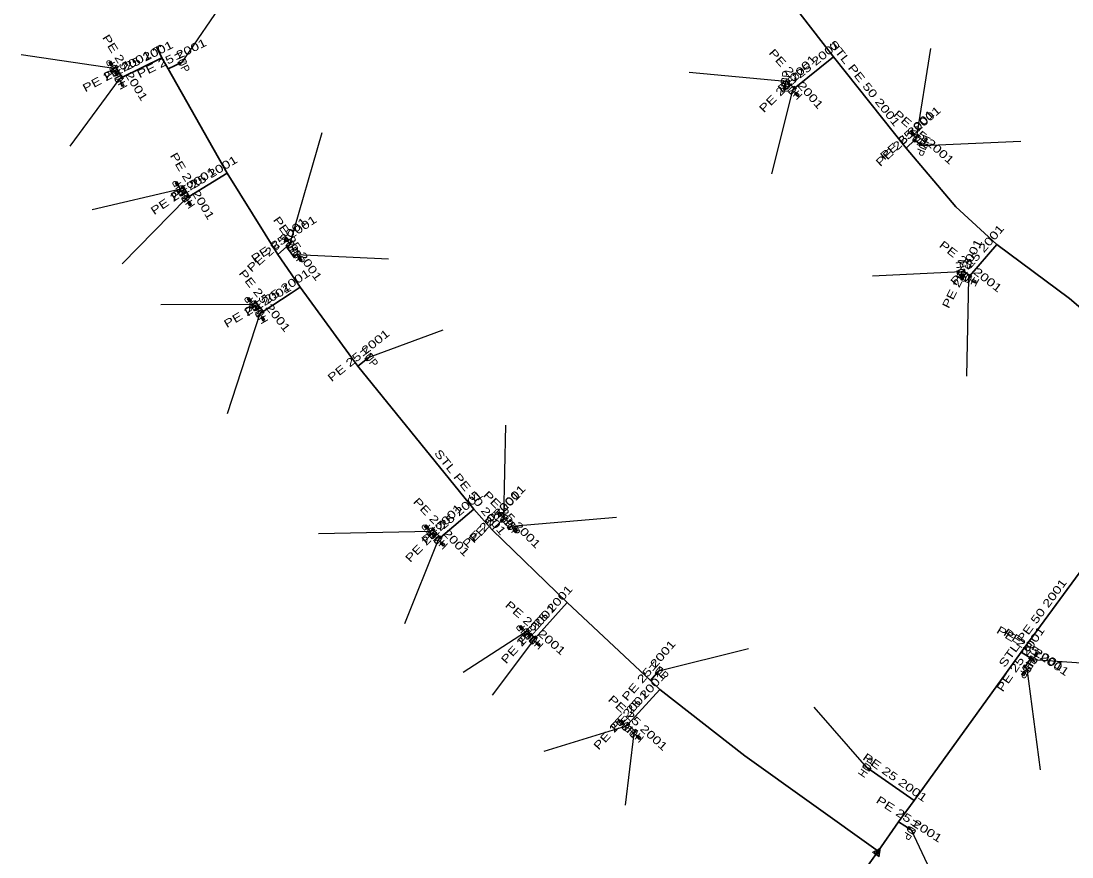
# Model space of a CAD drawing. Extents: x -737484 to -734496, y -1033882 to -1030666.
# Drawn here: x -735033.7 to -734902.5, y -1033583 to -1033478.6 of the extents above; entities that cross this region are included whole.
import ezdxf
from ezdxf.enums import TextEntityAlignment as Align

# ---------------------------------------------------------------- set-up
doc = ezdxf.new("R2010")
doc.units = 0
doc.header["$LTSCALE"] = 0.4
for name, color, linetype, lineweight in [('1', 7, 'Continuous', 13), ('22', 7, 'Continuous', 25), ('5', 7, 'Continuous', 35), ('7', 7, 'Continuous', 35)]:
    doc.layers.add(name, color=color, linetype=linetype, lineweight=lineweight)
doc.layers.add('2', color=7, linetype='Continuous')

msp = doc.modelspace()

# ---------------------------------------------------------------- linework, layer by layer
at = {"layer": '1'}
for p, q in [((-735022.361, -1033484.052), (-735022.546, -1033483.755)), ((-735022.12, -1033484.58), (-735022.384, -1033484.155)), ((-735021.46, -1033485.88), (-735021.225, -1033486.321)), ((-735021.256, -1033486.422), (-735021.091, -1033486.731)), ((-734938.27, -1033486.19), (-734938.313, -1033486.688)), ((-734938.394, -1033486.756), (-734938.425, -1033487.104)), ((-734937.37, -1033487.27), (-734937.016, -1033487.623)), ((-734937.016, -1033487.729), (-734936.768, -1033487.977)), ((-734922.22, -1033492.806), (-734922.45, -1033492.542)), ((-734921.9, -1033493.29), (-734922.228, -1033492.912)), ((-734921.06, -1033494.19), (-734920.864, -1033493.729)), ((-734920.766, -1033493.69), (-734920.629, -1033493.367)), ((-735014.07, -1033499.086), (-735014.26, -1033498.793)), ((-735013.82, -1033499.61), (-735014.092, -1033499.19)), ((-735013.11, -1033500.78), (-735012.83, -1033501.194)), ((-735012.85, -1033501.298), (-735012.654, -1033501.588)), ((-735000.4, -1033506.026), (-735000.59, -1033505.733)), ((-735000.15, -1033506.55), (-735000.422, -1033506.13)), ((-734999.33, -1033507.76), (-734999.043, -1033508.169)), ((-734999.061, -1033508.274), (-734998.86, -1033508.56)), ((-734916.33, -1033509.94), (-734916.26, -1033510.435)), ((-734916.324, -1033510.519), (-734916.275, -1033510.866)), ((-734915.39, -1033510.78), (-734914.944, -1033511.006)), ((-734914.911, -1033511.107), (-734914.599, -1033511.266)), ((-735005.05, -1033513.526), (-735005.28, -1033513.262)), ((-735004.73, -1033514.01), (-735005.058, -1033513.632)), ((-735003.91, -1033515.15), (-735003.66, -1033515.583)), ((-735003.687, -1033515.685), (-735003.512, -1033515.988)), ((-734973.781, -1033540.256), (-734974.033, -1033540.013)), ((-734982.905, -1033541.884), (-734983.148, -1033541.632)), ((-734973.42, -1033540.71), (-734973.779, -1033540.362)), ((-734982.56, -1033542.35), (-734982.907, -1033541.99)), ((-734972.52, -1033541.67), (-734972.191, -1033542.047)), ((-734972.199, -1033542.153), (-734971.969, -1033542.417)), ((-734981.63, -1033543.39), (-734981.27, -1033543.737)), ((-734981.268, -1033543.843), (-734981.016, -1033544.086)), ((-734971.077, -1033554.458), (-734971.315, -1033554.202)), ((-734970.74, -1033554.93), (-734971.08, -1033554.564)), ((-734969.72, -1033555.89), (-734969.348, -1033556.224)), ((-734969.342, -1033556.33), (-734969.082, -1033556.564)), ((-734907.33, -1033558.33), (-734907.072, -1033557.901)), ((-734906.969, -1033557.875), (-734906.789, -1033557.575)), ((-734908.48, -1033559.884), (-734908.66, -1033560.184)), ((-734908.12, -1033559.43), (-734908.377, -1033559.858)), ((-734958.559, -1033566.239), (-734958.831, -1033566.019)), ((-734958.16, -1033566.66), (-734958.548, -1033566.345)), ((-734957.18, -1033567.53), (-734956.802, -1033567.858)), ((-734956.795, -1033567.963), (-734956.531, -1033568.193))]:
    msp.add_line(p, q, dxfattribs=at)
msp.add_lwpolyline([(-735017.162, -1033482.329), (-735017.275, -1033482.106), (-735016.384, -1033481.653), (-735016.27, -1033481.875)], dxfattribs=at)
for points in [[(-735022.649, -1033483.731), (-735022.777, -1033483.811), (-735022.512, -1033484.235), (-735022.384, -1033484.155)], [(-735022.649, -1033483.731), (-735022.522, -1033483.652), (-735022.257, -1033484.076), (-735022.384, -1033484.155)], [(-735022.598, -1033483.744), (-735022.534, -1033483.704), (-735022.309, -1033484.065), (-735022.373, -1033484.104)], [(-735013.248, -1033483.371), (-735013.072, -1033483.73), (-735014.147, -1033483.809), (-735013.971, -1033484.168)], [(-735022.453, -1033485.003), (-735022.653, -1033484.656), (-735021.586, -1033484.503), (-735021.786, -1033484.156)], [(-735021.807, -1033486.29), (-735021.995, -1033485.937), (-735020.924, -1033485.82), (-735021.112, -1033485.467)], [(-735020.99, -1033486.762), (-735021.122, -1033486.833), (-735021.357, -1033486.391), (-735021.225, -1033486.321)], [(-735021.041, -1033486.746), (-735021.107, -1033486.781), (-735021.306, -1033486.406), (-735021.24, -1033486.371)], [(-735020.99, -1033486.762), (-735020.858, -1033486.692), (-735021.092, -1033486.251), (-735021.225, -1033486.321)], [(-734938.784, -1033486.344), (-734938.749, -1033485.946), (-734937.788, -1033486.431), (-734937.753, -1033486.033)], [(-734938.357, -1033487.186), (-734938.506, -1033487.173), (-734938.463, -1033486.675), (-734938.313, -1033486.688)], [(-734938.39, -1033487.145), (-734938.465, -1033487.138), (-734938.428, -1033486.715), (-734938.353, -1033486.721)], [(-734938.357, -1033487.186), (-734938.207, -1033487.199), (-734938.164, -1033486.701), (-734938.313, -1033486.688)], [(-734937.581, -1033487.764), (-734937.863, -1033487.482), (-734936.874, -1033487.057), (-734937.156, -1033486.775)], [(-734936.662, -1033487.977), (-734936.768, -1033488.083), (-734937.122, -1033487.729), (-734937.016, -1033487.623)], [(-734936.715, -1033487.976), (-734936.768, -1033488.029), (-734937.069, -1033487.728), (-734937.016, -1033487.675)], [(-734936.662, -1033487.977), (-734936.556, -1033487.871), (-734936.91, -1033487.517), (-734937.016, -1033487.623)], [(-734922.556, -1033492.535), (-734922.669, -1033492.633), (-734922.341, -1033493.011), (-734922.228, -1033492.912)], [(-734922.556, -1033492.535), (-734922.442, -1033492.436), (-734922.114, -1033492.814), (-734922.228, -1033492.912)], [(-734922.503, -1033492.539), (-734922.446, -1033492.49), (-734922.167, -1033492.811), (-734922.224, -1033492.86)], [(-734921.653, -1033492.811), (-734921.391, -1033493.112), (-734922.408, -1033493.467), (-734922.146, -1033493.768)], [(-734920.521, -1033494.2), (-734920.677, -1033494.568), (-734921.442, -1033493.809), (-734921.598, -1033494.177)], [(-734920.669, -1033493.269), (-734920.807, -1033493.21), (-734921.002, -1033493.671), (-734920.864, -1033493.729)], [(-734920.669, -1033493.269), (-734920.531, -1033493.328), (-734920.726, -1033493.788), (-734920.864, -1033493.729)], [(-734920.65, -1033493.318), (-734920.581, -1033493.348), (-734920.747, -1033493.739), (-734920.816, -1033493.71)], [(-735014.364, -1033498.771), (-735014.49, -1033498.853), (-735014.218, -1033499.272), (-735014.092, -1033499.19)], [(-735014.364, -1033498.771), (-735014.238, -1033498.689), (-735013.966, -1033499.108), (-735014.092, -1033499.19)], [(-735014.129, -1033500.05), (-735014.347, -1033499.714), (-735013.29, -1033499.505), (-735013.508, -1033499.169)], [(-735014.312, -1033498.783), (-735014.25, -1033498.742), (-735014.018, -1033499.098), (-735014.081, -1033499.139)], [(-735013.412, -1033501.225), (-735013.636, -1033500.893), (-735012.583, -1033500.666), (-735012.807, -1033500.334)], [(-735012.55, -1033501.609), (-735012.675, -1033501.692), (-735012.954, -1033501.278), (-735012.83, -1033501.194)], [(-735012.602, -1033501.598), (-735012.664, -1033501.64), (-735012.902, -1033501.287), (-735012.84, -1033501.245)], [(-735012.55, -1033501.609), (-735012.426, -1033501.525), (-735012.706, -1033501.11), (-735012.83, -1033501.194)], [(-735000.694, -1033505.711), (-735000.82, -1033505.793), (-735000.548, -1033506.212), (-735000.422, -1033506.13)], [(-735000.694, -1033505.711), (-735000.568, -1033505.629), (-735000.296, -1033506.048), (-735000.422, -1033506.13)], [(-734999.838, -1033506.108), (-734999.62, -1033506.444), (-735000.677, -1033506.653), (-735000.459, -1033506.989)], [(-735000.642, -1033505.723), (-735000.58, -1033505.682), (-735000.348, -1033506.038), (-735000.411, -1033506.079)], [(-734999.034, -1033507.309), (-734998.804, -1033507.637), (-734999.853, -1033507.882), (-734999.623, -1033508.21)], [(-734998.756, -1033508.579), (-734998.879, -1033508.665), (-734999.166, -1033508.255), (-734999.043, -1033508.169)], [(-734998.808, -1033508.569), (-734998.869, -1033508.612), (-734999.113, -1033508.264), (-734999.052, -1033508.221)], [(-734998.756, -1033508.579), (-734998.633, -1033508.493), (-734998.92, -1033508.083), (-734999.043, -1033508.169)], [(-734915.861, -1033509.671), (-734915.806, -1033510.067), (-734916.851, -1033509.81), (-734916.796, -1033510.206)], [(-734916.19, -1033510.93), (-734916.339, -1033510.951), (-734916.408, -1033510.456), (-734916.26, -1033510.435)], [(-734916.232, -1033510.897), (-734916.307, -1033510.908), (-734916.366, -1033510.487), (-734916.291, -1033510.476)], [(-734916.19, -1033510.93), (-734916.042, -1033510.909), (-734916.111, -1033510.414), (-734916.26, -1033510.435)], [(-734915.438, -1033511.316), (-734915.795, -1033511.134), (-734914.984, -1033510.425), (-734915.341, -1033510.243)], [(-734914.498, -1033511.233), (-734914.567, -1033511.367), (-734915.012, -1033511.14), (-734914.944, -1033511.006)], [(-734914.549, -1033511.249), (-734914.583, -1033511.316), (-734914.962, -1033511.123), (-734914.928, -1033511.056)], [(-734914.498, -1033511.233), (-734914.43, -1033511.1), (-734914.876, -1033510.873), (-734914.944, -1033511.006)], [(-735005.386, -1033513.255), (-735005.499, -1033513.353), (-735005.171, -1033513.731), (-735005.058, -1033513.632)], [(-735005.386, -1033513.255), (-735005.272, -1033513.156), (-735004.944, -1033513.534), (-735005.058, -1033513.632)], [(-735005.333, -1033513.259), (-735005.276, -1033513.21), (-735004.997, -1033513.531), (-735005.054, -1033513.58)], [(-735004.976, -1033514.487), (-735005.238, -1033514.186), (-735004.221, -1033513.831), (-735004.483, -1033513.53)], [(-735004.243, -1033515.573), (-735004.443, -1033515.226), (-735003.376, -1033515.073), (-735003.576, -1033514.726)], [(-735003.41, -1033516.016), (-735003.539, -1033516.091), (-735003.789, -1033515.658), (-735003.66, -1033515.583)], [(-735003.461, -1033516.001), (-735003.525, -1033516.039), (-735003.738, -1033515.671), (-735003.673, -1033515.633)], [(-735003.41, -1033516.016), (-735003.28, -1033515.941), (-735003.53, -1033515.508), (-735003.66, -1033515.583)], [(-734989.996, -1033520.129), (-734989.744, -1033520.44), (-734990.773, -1033520.759), (-734990.521, -1033521.07)], [(-734974.139, -1033540.015), (-734974.243, -1033540.123), (-734973.883, -1033540.47), (-734973.779, -1033540.362)], [(-734974.139, -1033540.015), (-734974.035, -1033539.907), (-734973.675, -1033540.254), (-734973.779, -1033540.362)], [(-734974.086, -1033540.015), (-734974.034, -1033539.961), (-734973.728, -1033540.256), (-734973.78, -1033540.31)], [(-734973.215, -1033540.21), (-734972.927, -1033540.488), (-734973.91, -1033540.929), (-734973.622, -1033541.207)], [(-734983.254, -1033541.63), (-734983.362, -1033541.734), (-734983.015, -1033542.094), (-734982.907, -1033541.99)], [(-734983.254, -1033541.63), (-734983.146, -1033541.526), (-734982.799, -1033541.886), (-734982.907, -1033541.99)], [(-734983.201, -1033541.632), (-734983.147, -1033541.58), (-734982.852, -1033541.885), (-734982.906, -1033541.938)], [(-734972.272, -1033541.191), (-734972.01, -1033541.492), (-734973.027, -1033541.847), (-734972.765, -1033542.148)], [(-734982.779, -1033542.84), (-734983.057, -1033542.552), (-734982.06, -1033542.145), (-734982.338, -1033541.857)], [(-734981.833, -1033543.887), (-734982.121, -1033543.609), (-734981.138, -1033543.168), (-734981.426, -1033542.89)], [(-734971.863, -1033542.424), (-734971.977, -1033542.523), (-734972.305, -1033542.145), (-734972.191, -1033542.047)], [(-734971.916, -1033542.42), (-734971.973, -1033542.469), (-734972.252, -1033542.148), (-734972.195, -1033542.099)], [(-734971.863, -1033542.424), (-734971.75, -1033542.326), (-734972.078, -1033541.948), (-734972.191, -1033542.047)], [(-734980.91, -1033544.084), (-734981.014, -1033544.192), (-734981.374, -1033543.845), (-734981.27, -1033543.737)], [(-734980.963, -1033544.084), (-734981.015, -1033544.138), (-734981.321, -1033543.843), (-734981.269, -1033543.789)], [(-734980.91, -1033544.084), (-734980.806, -1033543.976), (-734981.166, -1033543.629), (-734981.27, -1033543.737)], [(-734971.421, -1033554.198), (-734971.531, -1033554.3), (-734971.19, -1033554.666), (-734971.08, -1033554.564)], [(-734971.421, -1033554.198), (-734971.312, -1033554.096), (-734970.971, -1033554.462), (-734971.08, -1033554.564)], [(-734971.369, -1033554.201), (-734971.314, -1033554.15), (-734971.024, -1033554.46), (-734971.079, -1033554.512)], [(-734970.959, -1033555.421), (-734971.237, -1033555.133), (-734970.24, -1033554.726), (-734970.518, -1033554.438)], [(-734969.904, -1033556.395), (-734970.202, -1033556.127), (-734969.235, -1033555.652), (-734969.533, -1033555.384)], [(-734968.976, -1033556.559), (-734969.077, -1033556.67), (-734969.448, -1033556.336), (-734969.348, -1033556.224)], [(-734969.029, -1033556.561), (-734969.08, -1033556.616), (-734969.395, -1033556.332), (-734969.345, -1033556.276)], [(-734968.976, -1033556.559), (-734968.876, -1033556.447), (-734969.248, -1033556.113), (-734969.348, -1033556.224)], [(-734906.814, -1033557.472), (-734906.943, -1033557.395), (-734907.201, -1033557.824), (-734907.072, -1033557.901)], [(-734906.802, -1033558.443), (-734907.026, -1033558.775), (-734907.631, -1033557.884), (-734907.855, -1033558.216)], [(-734906.814, -1033557.472), (-734906.686, -1033557.55), (-734906.943, -1033557.978), (-734907.072, -1033557.901)], [(-734906.802, -1033557.524), (-734906.738, -1033557.563), (-734906.957, -1033557.927), (-734907.021, -1033557.888)], [(-734953.89, -1033559.218), (-734953.584, -1033559.475), (-734954.533, -1033559.984), (-734954.227, -1033560.241)], [(-734908.635, -1033560.287), (-734908.763, -1033560.209), (-734908.506, -1033559.781), (-734908.377, -1033559.858)], [(-734908.647, -1033560.235), (-734908.711, -1033560.196), (-734908.492, -1033559.832), (-734908.428, -1033559.871)], [(-734907.588, -1033559.515), (-734907.794, -1033559.857), (-734908.445, -1033559), (-734908.651, -1033559.342)], [(-734908.635, -1033560.287), (-734908.506, -1033560.364), (-734908.248, -1033559.935), (-734908.377, -1033559.858)], [(-734958.937, -1033566.03), (-734959.031, -1033566.147), (-734958.642, -1033566.461), (-734958.548, -1033566.345)], [(-734958.937, -1033566.03), (-734958.842, -1033565.914), (-734958.454, -1033566.228), (-734958.548, -1033566.345)], [(-734958.884, -1033566.025), (-734958.837, -1033565.967), (-734958.506, -1033566.235), (-734958.554, -1033566.293)], [(-734958.345, -1033567.165), (-734958.643, -1033566.897), (-734957.676, -1033566.422), (-734957.974, -1033566.154)], [(-734957.357, -1033568.038), (-734957.658, -1033567.776), (-734956.701, -1033567.283), (-734957.002, -1033567.021)], [(-734956.425, -1033568.186), (-734956.523, -1033568.299), (-734956.901, -1033567.971), (-734956.802, -1033567.858)], [(-734956.425, -1033568.186), (-734956.326, -1033568.072), (-734956.704, -1033567.744), (-734956.802, -1033567.858)], [(-734956.478, -1033568.189), (-734956.527, -1033568.245), (-734956.848, -1033567.966), (-734956.798, -1033567.91)], [(-734928.613, -1033571.667), (-734928.383, -1033571.339), (-734927.794, -1033572.24), (-734927.564, -1033571.912)], [(-734922.021, -1033579.703), (-734922.239, -1033580.039), (-734922.86, -1033579.158), (-734923.078, -1033579.494)], [(-734927.368, -1033582.35), (-734926.559, -1033582.938), (-734926.376, -1033581.835)], [(-734926.631, -1033582.762), (-734926.507, -1033582.016), (-734927.178, -1033582.364)], [(-734926.638, -1033582.197), (-734926.988, -1033582.379), (-734926.703, -1033582.586)]]:
    msp.add_lwpolyline(points, close=True, dxfattribs=at)
at = {"layer": '22'}
for p, q in [((-735013.61, -1033483.77), (-735005.67, -1033472.203)), ((-734921.9, -1033493.29), (-734920.088, -1033482.088)), ((-735022.12, -1033484.58), (-735033.731, -1033482.873)), ((-734938.269, -1033486.189), (-734950.288, -1033485.072)), ((-735021.46, -1033485.879), (-735027.645, -1033494.264)), ((-734937.369, -1033487.27), (-734940.022, -1033497.725)), ((-735000.149, -1033506.549), (-734996.125, -1033492.547)), ((-734921.06, -1033494.189), (-734908.868, -1033493.649)), ((-735013.819, -1033499.61), (-735024.836, -1033502.222)), ((-735013.11, -1033500.78), (-735021.091, -1033508.932)), ((-734999.329, -1033507.76), (-734987.855, -1033508.308)), ((-734916.329, -1033509.939), (-734927.369, -1033510.497)), ((-734915.39, -1033510.78), (-734915.665, -1033522.98)), ((-735004.73, -1033514.009), (-735016.254, -1033514.081)), ((-735003.91, -1033515.15), (-735007.984, -1033527.657)), ((-734990.259, -1033520.6), (-734980.989, -1033517.202)), ((-734973.419, -1033540.709), (-734973.187, -1033529.061)), ((-734972.519, -1033541.67), (-734959.36, -1033540.578)), ((-734982.559, -1033542.349), (-734996.593, -1033542.637)), ((-734981.63, -1033543.389), (-734985.826, -1033553.872)), ((-734970.739, -1033554.93), (-734978.492, -1033559.957)), ((-734969.719, -1033555.89), (-734974.903, -1033562.766)), ((-734954.059, -1033559.73), (-734942.893, -1033556.967)), ((-734907.329, -1033558.33), (-734897.972, -1033558.954)), ((-734908.12, -1033559.429), (-734906.46, -1033572.111)), ((-734928.089, -1033571.79), (-734934.684, -1033564.259)), ((-734958.16, -1033566.66), (-734968.432, -1033569.823)), ((-734957.18, -1033567.53), (-734958.285, -1033576.507)), ((-734922.55, -1033579.599), (-734918.344, -1033588.451))]:
    msp.add_line(p, q, dxfattribs=at)
at = {"layer": '5'}
for points in [[(-734886.84, -1033526.23), (-734891.99, -1033522.23), (-734897.89, -1033517.48), (-734902.77, -1033513.28), (-734911.87, -1033506.52), (-734916.99, -1033501.82), (-734923.19, -1033494.5), (-734932.27, -1033483.13), (-734945.44, -1033466.05), (-734949.38, -1033460.4), (-734951.95, -1033455.3), (-734960.07, -1033438.95), (-734960.25, -1033438.4)], [(-734926.67, -1033582.24), (-734943.33, -1033570.34), (-734953.95, -1033562.05), (-734955.1, -1033560.95), (-734965.53, -1033551.21), (-734974.88, -1033542.16), (-734977.17, -1033539.58), (-734991.65, -1033521.72), (-734998.87, -1033511.85), (-735000, -1033510.189), (-735001.64, -1033507.78), (-735007.97, -1033497.65), (-735015.34, -1033484.61), (-735016.13, -1033483.25), (-735016.83, -1033481.88)], [(-734926.67, -1033582.24), (-734924.14, -1033578.58), (-734922.19, -1033575.93), (-734908.82, -1033557.42), (-734899.167, -1033544.264), (-734895.087, -1033538.437), (-734887.55, -1033527.55), (-734886.84, -1033526.23)], [(-734975.96, -1033649.73), (-734970.39, -1033642.64), (-734966.67, -1033637.22), (-734956.36, -1033623.36), (-734942.15, -1033603.26), (-734941.29, -1033602.08), (-734933.89, -1033592.31), (-734926.67, -1033582.24)]]:
    msp.add_lwpolyline(points, dxfattribs=at)
at = {"layer": '7'}
for p, q in [((-735016.13, -1033483.25), (-735021.14, -1033485.71)), ((-735015.34, -1033484.61), (-735013.61, -1033483.77)), ((-734932.27, -1033483.13), (-734937.18, -1033487.08)), ((-735021.14, -1033485.71), (-735021.46, -1033485.879)), ((-734937.18, -1033487.08), (-734937.369, -1033487.27)), ((-734923.19, -1033494.5), (-734922.11, -1033493.47)), ((-734922.11, -1033493.47), (-734921.9, -1033493.29)), ((-735007.97, -1033497.65), (-735012.74, -1033500.53)), ((-735012.74, -1033500.53), (-735013.11, -1033500.78)), ((-735001.64, -1033507.78), (-735000.56, -1033506.82)), ((-735000.56, -1033506.82), (-735000.149, -1033506.549)), ((-734911.87, -1033506.52), (-734915.23, -1033510.46)), ((-734915.23, -1033510.46), (-734915.39, -1033510.78)), ((-735003.5, -1033514.91), (-735003.91, -1033515.15)), ((-734991.65, -1033521.72), (-734990.259, -1033520.6)), ((-734977.17, -1033539.58), (-734981.35, -1033543.1)), ((-734974.88, -1033542.16), (-734973.69, -1033540.99)), ((-734973.69, -1033540.99), (-734973.419, -1033540.709)), ((-734981.35, -1033543.1), (-734981.63, -1033543.389)), ((-734965.53, -1033551.21), (-734969.52, -1033555.67)), ((-734969.52, -1033555.67), (-734969.719, -1033555.89)), ((-734908.82, -1033557.42), (-734907.6, -1033558.15)), ((-734907.6, -1033558.15), (-734907.329, -1033558.33)), ((-734955.1, -1033560.95), (-734954.059, -1033559.73)), ((-734953.95, -1033562.05), (-734957.95, -1033566.43)), ((-734957.95, -1033566.43), (-734958.16, -1033566.66)), ((-734922.19, -1033575.93), (-734928.089, -1033571.79)), ((-734924.14, -1033578.58), (-734922.55, -1033579.599))]:
    msp.add_line(p, q, dxfattribs=at)
for points in [[(-735021.14, -1033485.71), (-735021.91, -1033484.46), (-735022.12, -1033484.58)], [(-734937.18, -1033487.08), (-734937.94, -1033486.22), (-734938.269, -1033486.189)], [(-734922.11, -1033493.47), (-734921.49, -1033494.01), (-734921.06, -1033494.189)], [(-735012.74, -1033500.53), (-735013.43, -1033499.36), (-735013.819, -1033499.61)], [(-735000.56, -1033506.82), (-735000, -1033507.617), (-734999.71, -1033508.03), (-734999.329, -1033507.76)], [(-734916.329, -1033509.939), (-734915.96, -1033509.89), (-734915.23, -1033510.46)], [(-734998.87, -1033511.85), (-735000, -1033512.596), (-735003.5, -1033514.91)], [(-735003.5, -1033514.91), (-735004.42, -1033513.74), (-735004.73, -1033514.009)], [(-734973.69, -1033540.99), (-734972.78, -1033541.9), (-734972.519, -1033541.67)], [(-734981.35, -1033543.1), (-734982.3, -1033542.1), (-734982.559, -1033542.349)], [(-734969.52, -1033555.67), (-734970.56, -1033554.76), (-734970.739, -1033554.93)], [(-734907.6, -1033558.15), (-734908.37, -1033559.28), (-734908.12, -1033559.429)], [(-734957.95, -1033566.43), (-734956.99, -1033567.31), (-734957.18, -1033567.53)]]:
    msp.add_lwpolyline(points, dxfattribs=at)

# ---------------------------------------------------------------- texts
at = {"layer": '2', "width": 0.95}
for rotation, p in [(296, (-735014.0585, -1033483.9883)), (120, (-735021.6861, -1033484.3295)), (118, (-735021.018, -1033485.6432)), (85, (-734937.7703, -1033486.2321)), (135, (-734937.0149, -1033486.9161)), (311, (-734922.2764, -1033493.6175)), (247, (-734921.5193, -1033493.9931)), (123, (-735013.3999, -1033499.3368)), (124, (-735012.6949, -1033500.5001)), (303, (-735000.5671, -1033506.8212)), (305, (-734999.7381, -1033508.0467)), (278, (-734916.8233, -1033510.0079)), (153, (-734915.1625, -1033510.3335)), (131, (-735004.3526, -1033513.6805)), (120, (-735003.4761, -1033514.8995)), (309, (-734990.6472, -1033520.9138)), (316, (-734973.7658, -1033541.0684)), (134, (-734982.1984, -1033542.0018)), (311, (-734972.8954, -1033541.9975)), (136, (-734981.2822, -1033543.0286)), (134, (-734970.3784, -1033554.5828)), (138, (-734969.3839, -1033555.5183)), (236, (-734907.7429, -1033558.0499)), (320, (-734954.3799, -1033560.1126)), (239, (-734908.5482, -1033559.171)), (138, (-734957.8249, -1033566.2883)), (139, (-734956.8515, -1033567.1524)), (55, (-734927.6791, -1033572.0763)), (237, (-734922.9689, -1033579.3262))]:
    msp.add_text('HUP', height=1, rotation=rotation, dxfattribs=at).set_placement(p, align=Align.CENTER)
at = {"layer": '5', "width": 1.35}
for rotation, p in [(308.611, (-734928.7706, -1033486.71)), (309.033, (-734978.0124, -1033537.7466)), (53.731, (-734906.9752, -1033554.0608))]:
    msp.add_text('STL PE 50 2001', height=1, rotation=rotation, dxfattribs=at).set_placement(p, align=Align.CENTER)
at = {"layer": '7', "width": 1.35}
for rotation, p in [(301.633, (-735021.1623, -1033484.7198)), (26.152, (-735018.8544, -1033484.0302)), (25.899, (-735014.6924, -1033483.74)), (38.816, (-734935.0384, -1033484.7149)), (27.84, (-735021.533, -1033485.3517)), (311.468, (-734937.2936, -1033486.1954)), (45.151, (-734937.6287, -1033486.8221)), (43.643, (-734922.9951, -1033493.6231)), (40.601, (-734922.3299, -1033492.9995)), (318.945, (-734921.2954, -1033493.5157)), (300.53, (-735012.7712, -1033499.4915)), (31.122, (-735010.6129, -1033498.6615)), (34.046, (-735013.2044, -1033500.2407)), (41.634, (-735001.4322, -1033506.9258)), (33.4, (-735000.6297, -1033506.2669)), (305.093, (-734999.5915, -1033507.328)), (49.543, (-734913.9297, -1033508.1654)), (322.017, (-734915.4337, -1033509.6655)), (63.435, (-734915.7568, -1033510.3956)), (308.179, (-735003.6941, -1033513.8539)), (33.47, (-735001.4608, -1033512.9619)), (30.343, (-735003.9571, -1033514.5986)), (38.84, (-734991.2676, -1033520.7702)), (40.101, (-734979.5816, -1033540.9572)), (44.514, (-734974.635, -1033541.2176)), (46.038, (-734973.9139, -1033540.5021)), (315, (-734972.7581, -1033541.2139)), (313.531, (-734981.5858, -1033542.1251)), (45.906, (-734981.8484, -1033542.8959)), (48.184, (-734967.8973, -1033553.1059)), (47.869, (-734969.9903, -1033555.4444)), (318.814, (-734969.8028, -1033554.7566)), (55.729, (-734908.4792, -1033558.5536)), (329.105, (-734907.9527, -1033557.3557)), (326.408, (-734907.1871, -1033557.8236)), (49.527, (-734954.9595, -1033560.015)), (47.596, (-734956.3183, -1033563.9022)), (47.603, (-734958.424, -1033566.2071)), (317.49, (-734957.0244, -1033566.5989)), (324.938, (-734924.8517, -1033573.4502)), (327.345, (-734923.0743, -1033578.6678))]:
    msp.add_text('PE 25 2001', height=1, rotation=rotation, dxfattribs=at).set_placement(p, align=Align.CENTER)

doc.saveas('drawing.dxf')
